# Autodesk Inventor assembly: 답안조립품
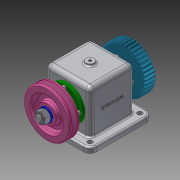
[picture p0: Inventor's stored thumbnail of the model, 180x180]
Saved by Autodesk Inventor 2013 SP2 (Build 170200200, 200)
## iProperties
Created: 2022-07
Part Number: 답안조립품
Document SubType Name: Assembly
Designer: i
Author: i
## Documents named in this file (12)
- C:\Users\i\Desktop\720706V1009\답안조립품.iam
- C:\Users\i\Desktop\720706V1009\본체.ipt
- C:\Users\i\Desktop\720706V1009\V벨트풀리.ipt
- C:\Users\i\Desktop\720706V1009\너트 M12x1.25.ipt
- C:\Users\i\Desktop\720706V1009\베어링 6204.ipt
- C:\Users\i\Desktop\720706V1009\볼트 M4x0.7.ipt
- C:\Users\i\Desktop\720706V1009\스퍼기어.ipt
- C:\Users\i\Desktop\720706V1009\오일실 20x35x8.ipt
- C:\Users\i\Desktop\720706V1009\와셔 12x24.ipt
- C:\Users\i\Desktop\720706V1009\축.ipt
- C:\Users\i\Desktop\720706V1009\커버.ipt
- C:\Users\i\Desktop\720706V1009\키 5x5.ipt
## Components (1 placed, 1 different names)
1. V벨트풀리:1
